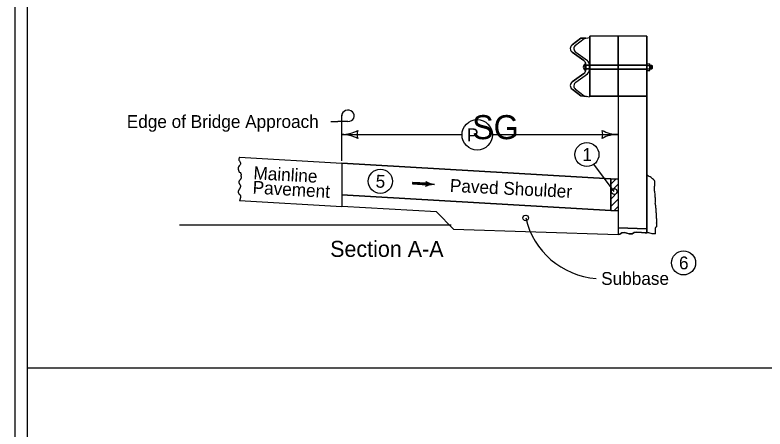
# Model space of a CAD drawing. Extents: x 9538 to 81668, y 7600 to 11751.
# Drawn here: x 13733 to 14667, y 8764 to 9280 of the extents above; entities that cross this region are included whole.
import ezdxf

# ---------------------------------------------------------------- set-up
doc = ezdxf.new("R2010")
doc.units = 0
for name, color, linetype in [('Default', 7, 'Continuous'), ('DsnShtMinorGrid13', 7, 'Continuous'), ('DsnShtMinorGrid14', 7, 'Continuous'), ('dsnStdCells', 7, 'Continuous'), ('dsnStdDimension', 7, 'Continuous'), ('dsnStdNameDate', 7, 'Continuous'), ('dsnStdNote', 7, 'Continuous'), ('dsnStdShading', 7, 'Continuous'), ('dsnStdTable', 7, 'Continuous')]:
    doc.layers.add(name, color=color, linetype=linetype)

msp = doc.modelspace()

# ---------------------------------------------------------------- linework, layer by layer
at = {"layer": 'Default'}
msp.add_lwpolyline([(13732.53, 9944.02), (16867.53, 9944.02), (16867.53, 7924.02), (13732.53, 7924.02)], close=True, dxfattribs=at)
at = {"layer": 'DsnShtMinorGrid13'}
for centre, radius in [((14444.79, 9106.23), 15), ((14187.58, 9072.86), 15), ((14478.92, 9060.11), 3.58), ((14565.23, 8971.18), 15)]:
    msp.add_circle(centre, radius, dxfattribs=at)
at = {"layer": 'DsnShtMinorGrid14'}
msp.add_circle((14368.6, 9027.15), 3.54, dxfattribs=at)
at = {"layer": 'dsnStdCells'}
for p, q in [((14426.56, 9233.67), (14441.07, 9223.26)), ((14441.07, 9207.18), (14426.56, 9196.77))]:
    msp.add_line(p, q, dxfattribs=at)
for points in [[(14430.81, 9242.57), (14430.8, 9242.56), (14441.57, 9250.97), (14443.46, 9251.3), (14437.13, 9251.19), (14426.37, 9242.79)], [(14483.85, 9217.88), (14483.85, 9253.55), (14448.31, 9253.55), (14448.31, 9217.88), (14448.31, 9217.88), (14483.85, 9217.88)], [(14519.4, 9217.88), (14519.4, 9221.88), (14519.4, 9253.55), (14483.85, 9253.55), (14483.85, 9217.88), (14519.4, 9217.88)], [(14445.51, 9223.04), (14445.54, 9223.02), (14430.98, 9233.48), (14431.01, 9233.45)], [(14443.46, 9218.63), (14443.46, 9217.55), (14447.91, 9217.55), (14447.91, 9218.41), (14447.91, 9218.41)], [(14447.91, 9211.6), (14447.91, 9211.6), (14447.91, 9212.88), (14443.47, 9212.88), (14443.47, 9211.82), (14443.47, 9212.88), (14443.46, 9212.88), (14443.46, 9211.82)], [(14448.31, 9217.55), (14448.31, 9212.88), (14448.31, 9212.88), (14483.85, 9212.88), (14483.85, 9217.55), (14448.31, 9217.55), (14448.31, 9217.55)], [(14448.31, 9212.55), (14448.31, 9178.9), (14483.85, 9178.9), (14483.85, 9212.55), (14448.31, 9212.55)], [(14519.4, 9212.88), (14519.4, 9217.55), (14483.85, 9217.55), (14483.85, 9212.88), (14519.4, 9212.88)], [(14519.4, 9178.9), (14519.4, 9208.55), (14519.4, 9212.55), (14483.85, 9212.55), (14483.85, 9178.9), (14519.4, 9178.9)], [(14431.01, 9196.55), (14430.98, 9196.53), (14445.54, 9206.99), (14445.51, 9206.96)], [(14426.37, 9187.65), (14437.13, 9179.25), (14444.23, 9178.56), (14441.57, 9179.03), (14430.8, 9187.44), (14430.81, 9187.43)], [(14519.4, 9013.57), (14519.4, 9178.9), (14483.85, 9178.9), (14483.85, 9075.94), (14483.85, 9069.25), (14483.85, 9069.25), (14483.85, 9069.25), (14483.85, 9060.02), (14483.85, 9060.02), (14483.85, 9060.02), (14483.85, 9050.88), (14483.85, 9050.88), (14483.85, 9050.88), (14483.85, 9043.95), (14483.85, 9014.73), (14519.4, 9013.57)], [(14519.4, 9013.57), (14483.85, 9014.73), (14483.85, 9006.67), (14485.66, 9006.92), (14488.42, 9008.51), (14491.71, 9009.04), (14497.32, 9007.45), (14501.03, 9007.24), (14503.68, 9009.04), (14506.76, 9009.68), (14513.01, 9008.94), (14517.25, 9008.51), (14519.4, 9008.51), (14519.4, 9013.57)]]:
    msp.add_lwpolyline(points, dxfattribs=at)
msp.add_lwpolyline([(14447.91, 9217.55), (14443.46, 9217.55), (14443.47, 9214.09), (14443.47, 9215.22), (14443.47, 9212.88), (14447.91, 9212.88)], close=True, dxfattribs=at)
for centre, start, end in [((14429.84, 9238.31), 127.75002, 234.69086), ((14434.29, 9238.09), 127.75002, 234.69086), ((14437.79, 9218.63), 0, 54.69099), ((14442.23, 9218.41), 0, 54.69099), ((14437.79, 9211.82), 305.30901, 0), ((14442.23, 9211.6), 305.30901, 0), ((14429.84, 9192.14), 125.30914, 232.24998), ((14434.29, 9191.92), 125.30914, 232.24998)]:
    msp.add_arc(centre, 5.68, start, end, dxfattribs=at)
at = {"layer": 'dsnStdDimension'}
for p, q in [((14139.46, 9131.19), (14289.29, 9131.19)), ((14327.15, 9131.34), (14483.85, 9131.34))]:
    msp.add_line(p, q, dxfattribs=at)
msp.add_circle((14308.22, 9130.78), 18.93, dxfattribs=at)
for centre, radius, start, end in [((14139.46, 9173.69), 42.5, 270, 298.07249), ((14175.1, 9131.19), 16.42, 162.26665, 197.73335), ((14448.22, 9131.34), 16.42, 342.26665, 17.73335), ((14483.85, 9173.84), 42.5, 241.92751, 270), ((14139.46, 9088.69), 42.5, 61.92751, 90), ((14483.85, 9088.84), 42.5, 90, 118.07249), ((14463.83, 9049.27), 97.76, 193.07698, 265.55799)]:
    msp.add_arc(centre, radius, start, end, dxfattribs=at)
at = {"layer": 'dsnStdNameDate'}
for p, q in [((14478.92, 9060.11), (14453.53, 9094.04)), ((15903.11, 8840.02), (13747.53, 8840.02))]:
    msp.add_line(p, q, dxfattribs=at)
at = {"layer": 'dsnStdNote'}
for p, q in [((14139.46, 9134.51), (14139.46, 9155.37)), ((14126.09, 9147.35), (14134.78, 9147.35)), ((14147.27, 9147.35), (14134.78, 9147.35)), ((14139.46, 9098.57), (14139.46, 9134.51)), ((14245.85, 9069.47), (14227.64, 9070.52)), ((14245.86, 9070.47), (14245.86, 9070.47)), ((14245.74, 9068.53), (14245.74, 9068.53))]:
    msp.add_line(p, q, dxfattribs=at)
for points in [[(14245.87, 9070.41), (14227.71, 9071.46), (14227.58, 9069.58), (14245.74, 9068.53), (14245.8, 9070.14), (14227.93, 9071.23), (14227.87, 9069.74), (14245.36, 9068.79), (14245.48, 9069.91), (14228.16, 9070.97), (14228.14, 9069.97), (14245.15, 9068.99), (14245.24, 9069.69), (14228.35, 9070.75), (14228.33, 9070.19), (14244.94, 9069.25)], [(14245.47, 9071.66), (14246.16, 9070.5), (14246.14, 9068.85), (14245.38, 9067.45), (14248.14, 9068.32), (14251.33, 9068.97), (14252.23, 9069.1), (14249.99, 9069.65), (14246.76, 9070.88), (14245.82, 9071.41), (14245.94, 9067.9), (14250.89, 9069.12), (14246.25, 9070.7), (14246.26, 9068.28), (14249.66, 9069.21), (14246.66, 9070.07), (14246.43, 9068.69), (14248.59, 9069.19), (14247, 9069.7), (14246.86, 9069.04), (14247.65, 9069.2)]]:
    msp.add_lwpolyline(points, dxfattribs=at)
for centre, major_axis, start_param, end_param in [((14147.27, 9154.49), (-7.81, 0), 1.570796, 6.283185), ((14242.08, 9069.68), (3.88, 0), 5.202895, 7.237436), ((14257.14, 9089.11), (-22.17, 0), 0.954258, 1.478381), ((14254.35, 9048.69), (22.17, 0), 1.537172, 2.061295)]:
    msp.add_ellipse(centre, major_axis=major_axis, ratio=0.913811, start_param=start_param, end_param=end_param, dxfattribs=at)
at = {"layer": 'dsnStdShading'}
msp.add_line((13747.53, 9929.02), (13747.53, 8319.02), dxfattribs=at)
at = {"layer": 'dsnStdTable'}
for p, q in [((14426.37, 9242.79), (14437.13, 9251.19)), ((14430.8, 9242.56), (14441.57, 9250.97)), ((14437.13, 9251.19), (14443.46, 9251.3)), ((14441.57, 9250.97), (14447.91, 9252.09)), ((14519.4, 9253.55), (14448.31, 9253.55)), ((14448.31, 9178.9), (14448.31, 9253.55)), ((14483.85, 9178.9), (14483.85, 9253.55)), ((14519.4, 9253.55), (14519.4, 9008.51)), ((14441.07, 9223.26), (14426.56, 9233.67)), ((14445.54, 9223.02), (14430.98, 9233.48)), ((14519.4, 9221.85), (14520.08, 9221.85)), ((14520.08, 9208.52), (14520.08, 9221.85)), ((14442.69, 9211.15), (14442.69, 9219.24)), ((14442.69, 9217.55), (14448.12, 9217.55)), ((14442.69, 9212.88), (14448.31, 9212.88)), ((14443.47, 9211.82), (14443.46, 9218.63)), ((14443.46, 9211.82), (14443.47, 9215.22)), ((14443.47, 9215.22), (14443.47, 9211.82)), ((14443.64, 9217.55), (14448.31, 9217.55)), ((14447.91, 9215), (14447.91, 9218.41)), ((14447.91, 9211.6), (14447.91, 9215)), ((14447.91, 9215), (14447.91, 9211.6)), ((14448.3, 9212.55), (14519.4, 9212.55)), ((14448.31, 9217.88), (14519.4, 9217.88)), ((14448.31, 9217.55), (14519.4, 9217.55)), ((14448.31, 9212.88), (14519.4, 9212.88)), ((14520.08, 9219.23), (14523.05, 9219.23)), ((14520.08, 9217.2), (14523.05, 9217.2)), ((14520.08, 9213.16), (14523.05, 9213.16)), ((14520.08, 9211.14), (14523.05, 9211.14)), ((14523.41, 9212.15), (14523.41, 9218.21)), ((14523.41, 9217.52), (14525.78, 9217.52)), ((14523.41, 9212.85), (14525.78, 9212.85)), ((14524.3, 9217.52), (14524.3, 9212.85)), ((14525.04, 9217.52), (14525.04, 9212.85)), ((14525.78, 9217.52), (14526.23, 9216.98)), ((14525.78, 9217.52), (14525.78, 9212.85)), ((14526.23, 9213.39), (14525.78, 9212.85)), ((14526.23, 9216.98), (14526.23, 9213.39)), ((14426.56, 9196.77), (14441.07, 9207.18)), ((14430.98, 9196.53), (14445.54, 9206.99)), ((14519.4, 9208.52), (14520.08, 9208.52)), ((14437.13, 9179.25), (14426.37, 9187.65)), ((14441.57, 9179.03), (14430.8, 9187.44)), ((14444.23, 9178.56), (14437.13, 9179.25)), ((14447.91, 9177.92), (14441.57, 9179.03)), ((14483.85, 9178.9), (14448.31, 9178.9)), ((14483.85, 9178.9), (14483.85, 9006.67)), ((14012, 9102.84), (14139.46, 9095.43)), ((14139.46, 9095.43), (14139.46, 9041.42)), ((14139.46, 9095.43), (14474.6, 9075.94)), ((14474.6, 9075.94), (14139.46, 9095.43)), ((14139.46, 9095.43), (14139.46, 9055.83)), ((14474.6, 9069.2), (14481.34, 9075.94)), ((14474.6, 9069.2), (14481.34, 9075.94)), ((14474.6, 9069.2), (14481.34, 9075.94)), ((14474.6, 9069.2), (14481.34, 9075.94)), ((14474.6, 9075.94), (14483.84, 9075.94)), ((14474.6, 9075.94), (14474.6, 9036.51)), ((14474.6, 9036.51), (14474.6, 9075.94)), ((14474.6, 9060.01), (14483.84, 9069.25)), ((14474.6, 9060.01), (14483.84, 9069.25)), ((14474.6, 9060.01), (14483.84, 9069.25)), ((14474.6, 9060.01), (14483.84, 9069.25)), ((14529.45, 9069.17), (14529.45, 9069.17)), ((14474.6, 9036.51), (14139.46, 9055.83)), ((14139.46, 9055.83), (14474.6, 9036.51)), ((14474.6, 9050.78), (14483.84, 9060.02)), ((14474.6, 9050.78), (14483.84, 9060.02)), ((14474.6, 9050.78), (14483.84, 9060.02)), ((14474.6, 9050.78), (14483.84, 9060.02)), ((14012.03, 9048.83), (14139.46, 9041.42)), ((14474.6, 9041.56), (14483.84, 9050.79)), ((14257.3, 9034.62), (14139.46, 9041.42)), ((14257.3, 9034.62), (14278.64, 9013.41)), ((14474.6, 9036.51), (14483.84, 9036.51)), ((14478.7, 9036.51), (14483.84, 9041.65)), ((13937.41, 9018.58), (14275.91, 9018.58)), ((14278.64, 9013.41), (14483.85, 9006.67))]:
    msp.add_line(p, q, dxfattribs=at)
for points in [[(14523.4, 9212.48), (14523.35, 9212.74), (14523.31, 9212.92), (14523.22, 9213.07), (14523.1, 9213.17), (14523.18, 9213.26), (14523.26, 9213.49), (14523.32, 9213.8), (14523.4, 9214.55), (14523.4, 9212.47), (14523.38, 9212.62), (14523.34, 9212.83), (14523.26, 9213.04), (14523.14, 9213.15), (14523.18, 9213.24), (14523.24, 9213.39), (14523.34, 9213.89), (14523.38, 9214.27), (14523.38, 9212.67), (14523.35, 9212.79), (14523.31, 9212.95), (14523.18, 9213.15), (14523.23, 9213.32), (14523.31, 9213.66), (14523.37, 9213.98), (14523.36, 9212.82), (14523.32, 9212.95), (14523.21, 9213.14), (14523.25, 9213.36), (14523.31, 9213.62), (14523.34, 9213.79), (14523.34, 9212.93), (14523.28, 9213.03), (14523.23, 9213.15), (14523.32, 9213.61), (14523.32, 9213.01), (14523.25, 9213.14), (14523.3, 9213.44), (14523.3, 9213.08), (14523.27, 9213.15), (14523.28, 9213.25), (14523.28, 9213.18)], [(14523.11, 9217.21), (14523.18, 9217.25), (14523.26, 9217.35), (14523.34, 9217.57), (14523.4, 9217.86), (14523.4, 9215.91), (14523.34, 9216.43), (14523.29, 9216.8), (14523.17, 9217.12), (14523.11, 9217.21), (14523.17, 9217.21), (14523.27, 9217.36), (14523.36, 9217.59), (14523.38, 9217.74), (14523.38, 9216.2), (14523.31, 9216.7), (14523.25, 9216.96), (14523.15, 9217.18), (14523.18, 9217.2), (14523.32, 9217.41), (14523.36, 9217.57), (14523.36, 9216.46), (14523.17, 9217.17), (14523.34, 9217.45), (14523.34, 9216.6), (14523.2, 9217.16), (14523.32, 9217.38), (14523.33, 9216.74), (14523.22, 9217.14), (14523.31, 9217.32), (14523.31, 9216.9), (14523.24, 9217.13), (14523.29, 9217.25), (14523.29, 9217.04), (14523.26, 9217.11), (14523.27, 9217.16)], [(14529.92, 9045.33), (14529.86, 9045.06), (14529.86, 9044.86), (14529.86, 9044.67), (14529.86, 9044.47), (14529.86, 9044.28), (14529.86, 9044.08), (14529.86, 9043.79), (14529.86, 9043.59), (14529.96, 9043.3), (14530.06, 9043.01), (14530.25, 9042.81), (14530.25, 9042.62), (14530.35, 9042.42), (14530.35, 9042.23), (14530.35, 9042.03), (14530.45, 9041.93), (14530.45, 9041.74), (14530.45, 9041.54), (14530.45, 9041.35), (14530.45, 9041.15), (14530.45, 9040.96), (14530.45, 9040.66), (14530.45, 9040.37), (14530.45, 9040.17), (14530.45, 9039.88), (14530.45, 9039.69), (14530.45, 9039.49), (14530.55, 9039.39), (14530.55, 9039.2), (14530.55, 9039), (14530.55, 9038.81), (14530.55, 9038.61), (14530.55, 9038.42), (14530.55, 9038.22), (14530.55, 9038.02), (14530.55, 9037.83), (14530.55, 9037.63), (14530.55, 9037.44), (14530.55, 9037.24), (14530.55, 9037.05), (14530.55, 9036.85), (14530.55, 9036.66), (14530.55, 9036.46), (14530.55, 9036.27), (14530.55, 9036.07), (14530.55, 9035.88), (14530.64, 9035.78), (14530.64, 9035.58), (14530.64, 9035.39), (14530.74, 9035.29), (14530.74, 9035.09), (14530.74, 9034.9), (14530.84, 9034.8), (14530.84, 9034.61), (14530.84, 9034.41), (14530.84, 9034.21), (14530.84, 9033.92), (14530.94, 9033.63), (14530.94, 9033.43), (14530.94, 9033.24), (14530.94, 9033.04), (14530.94, 9032.85), (14530.94, 9032.65), (14530.94, 9032.46), (14530.94, 9032.26), (14530.94, 9032.06), (14530.94, 9031.87), (14530.94, 9031.67), (14530.94, 9031.48), (14530.94, 9031.28), (14530.94, 9031.09), (14530.94, 9030.89), (14530.94, 9030.7), (14530.94, 9030.5), (14530.94, 9030.31), (14530.94, 9030.11), (14530.94, 9029.92), (14530.94, 9029.72), (14530.94, 9029.52), (14530.94, 9029.33), (14530.94, 9029.13), (14530.94, 9028.94), (14530.94, 9028.74), (14530.94, 9028.55), (14530.94, 9028.35), (14530.94, 9028.16), (14530.94, 9027.96), (14531.03, 9027.86), (14531.03, 9027.57), (14531.03, 9027.37), (14531.13, 9027.18), (14531.23, 9026.89), (14531.23, 9026.69), (14531.33, 9026.59), (14531.33, 9026.4), (14531.42, 9026.3), (14531.52, 9026.2), (14531.52, 9026.01), (14531.52, 9025.81), (14531.52, 9025.62), (14531.62, 9025.52), (14531.62, 9025.32), (14531.62, 9025.13), (14531.62, 9024.93), (14531.62, 9024.74), (14531.62, 9024.54), (14531.62, 9024.35), (14531.62, 9024.15), (14531.62, 9023.96), (14531.62, 9023.76), (14531.62, 9023.56), (14531.62, 9023.37), (14531.62, 9023.17), (14531.62, 9022.98), (14531.62, 9022.78), (14531.62, 9022.59), (14531.62, 9022.39), (14531.62, 9022.2), (14531.62, 9022), (14531.62, 9021.81), (14531.62, 9021.61), (14531.62, 9021.42), (14531.62, 9021.22), (14531.62, 9021.02), (14531.62, 9020.83), (14531.62, 9020.63), (14531.62, 9020.63), (14531.62, 9020.93), (14531.62, 9021.12), (14531.62, 9021.32), (14531.62, 9021.12), (14531.62, 9020.93), (14531.62, 9020.73), (14531.62, 9020.54), (14531.62, 9020.34), (14531.62, 9020.14), (14531.62, 9019.95), (14531.62, 9019.75), (14531.62, 9019.56), (14531.62, 9019.36), (14531.62, 9019.17), (14531.62, 9018.97), (14531.62, 9018.78), (14531.62, 9018.58), (14531.62, 9018.39), (14531.52, 9018.29), (14531.52, 9018.09), (14531.52, 9017.9), (14531.52, 9017.7), (14531.52, 9017.51), (14531.52, 9017.31), (14531.52, 9017.12), (14531.52, 9016.92), (14531.52, 9016.73), (14531.52, 9016.53), (14531.52, 9016.33), (14531.42, 9016.24), (14531.33, 9016.04), (14531.23, 9015.94), (14531.13, 9015.85), (14531.03, 9015.75), (14530.84, 9015.65), (14530.64, 9015.65), (14530.55, 9015.55), (14530.45, 9015.46), (14530.35, 9015.36), (14530.15, 9015.26), (14530.06, 9015.16), (14530.06, 9014.97), (14529.96, 9014.87), (14529.96, 9014.67), (14529.96, 9014.48), (14529.96, 9014.28), (14529.96, 9007.46)], [(14530.09, 9007.47), (14525.94, 9007.35), (14521.81, 9008.51), (14517.25, 9008.51), (14513.01, 9008.94), (14506.76, 9009.68), (14503.68, 9009.04), (14501.03, 9007.24), (14497.32, 9007.45), (14491.71, 9009.04), (14488.42, 9008.51), (14485.66, 9006.92), (14483.85, 9006.67)]]:
    msp.add_lwpolyline(points, dxfattribs=at)
msp.add_circle((14187.58, 9072.86), 15, dxfattribs=at)
for centre, radius, start, end in [((14429.84, 9238.31), 5.68, 127.75002, 234.69086), ((14434.29, 9238.09), 5.68, 127.75002, 234.69086), ((14437.79, 9218.63), 5.68, 360, 54.69099), ((14442.23, 9218.41), 5.68, 360, 54.69099), ((14444.77, 9215.2), 4.54, 117.20289, 242.8461), ((14437.79, 9211.82), 5.68, 305.30901, 0), ((14442.23, 9211.6), 5.68, 305.30901, 0), ((14429.84, 9192.14), 5.68, 125.30914, 232.24998), ((14434.29, 9191.92), 5.68, 125.30914, 232.24998)]:
    msp.add_arc(centre, radius, start, end, dxfattribs=at)
for centre in [(14523.05, 9218.21), (14523.05, 9212.15)]:
    msp.add_ellipse(centre, major_axis=(0, -1.01), ratio=0.362258, start_param=6.283156, end_param=9.424748, dxfattribs=at)
for points in [[(14012, 9102.84), (14011.5, 9099.24), (14012.54, 9097.73), (14013.4, 9095.44), (14012.8, 9093.38), (14010.89, 9091), (14010.37, 9089.1), (14010.89, 9086.8), (14011.76, 9084.43), (14012.8, 9083.72), (14014.18, 9081.18), (14014.17, 9080.34)], [(14012.21, 9063.23), (14012.42, 9063.48), (14012.62, 9063.74), (14012.97, 9064.3), (14013.25, 9064.89), (14013.37, 9065.19), (14013.47, 9065.51), (14013.6, 9066.13), (14013.65, 9066.75), (14013.6, 9067.34), (14013.54, 9067.61), (14013.51, 9067.75), (14013.46, 9067.88), (14013.25, 9068.26), (14012.97, 9068.62), (14012.67, 9068.99), (14012.42, 9069.38), (14012.28, 9069.67), (14012.14, 9069.95), (14011.88, 9070.52), (14011.68, 9071.09), (14011.61, 9071.38), (14011.55, 9071.68), (14011.54, 9071.81), (14011.54, 9071.94), (14011.69, 9072.71), (14011.9, 9073.23), (14012.16, 9073.74), (14012.6, 9074.38), (14013.12, 9074.92), (14013.64, 9075.47), (14013.87, 9075.78), (14014.07, 9076.12), (14014.27, 9076.59), (14014.43, 9077.06), (14014.53, 9077.54), (14014.57, 9077.78), (14014.58, 9077.9), (14014.59, 9078.02), (14014.54, 9078.53), (14014.39, 9079.04), (14014.34, 9079.17), (14014.28, 9079.29), (14014.23, 9079.42), (14014.21, 9079.55), (14014.17, 9080.34)], [(14529.92, 9045.33), (14530.24, 9048.24), (14530.02, 9053.1), (14529.58, 9058.85), (14528.91, 9063.27), (14529.13, 9066.59), (14529.58, 9070.79), (14528.91, 9073.89), (14526.7, 9075.88), (14524.71, 9077.65), (14522.5, 9078.75), (14520.29, 9080.08), (14519.41, 9080.74)], [(14012.21, 9063.23), (14011.99, 9062.99), (14011.75, 9062.76), (14011.51, 9062.52), (14011.33, 9062.25), (14011.19, 9061.97), (14011.05, 9061.68), (14010.79, 9061.11), (14010.68, 9060.83), (14010.58, 9060.54), (14010.51, 9060.25), (14010.48, 9060.1), (14010.46, 9059.95), (14010.47, 9059.44), (14010.6, 9058.92), (14010.81, 9058.4), (14011.07, 9057.89), (14011.51, 9057.26), (14012.03, 9056.71), (14012.55, 9056.16), (14012.78, 9055.86), (14012.98, 9055.52), (14013.38, 9054.57), (14013.49, 9054.1), (14013.5, 9053.62), (14013.46, 9053.33), (14013.41, 9053.04), (14013.36, 9052.75), (14013.29, 9052.47), (14012.98, 9051.32), (14012.8, 9050.71), (14012.6, 9050.11), (14012.38, 9049.52), (14012.25, 9049.23), (14012.11, 9048.94), (14012.03, 9048.83)]]:
    msp.add_spline(points, degree=3, dxfattribs=at)

# ---------------------------------------------------------------- texts
at = {"layer": 'DsnShtMinorGrid13'}
for s, p in [('1', (14439.17, 9098.23)), ('6', (14559.53, 8963.18))]:
    msp.add_text(s, height=16, dxfattribs=at).set_placement(p)
msp.add_text('5', height=16, rotation=356.69973, dxfattribs=at).set_placement((14181.36, 9065.2))
at = {"layer": 'dsnStdDimension'}
for s, height, p in [('SG', 30, (14301.94, 9125.34)), ('P', 16, (14295.51, 9122.78))]:
    msp.add_text(s, height=height, dxfattribs=at).set_placement(p)
at = {"layer": 'dsnStdNote'}
for s, height, p in [('Edge of Bridge Approach', 16, (13871.73, 9139.35)), ('Section A-A', 20, (14125.04, 8978.66)), ('Subbase', 16, (14462.61, 8943.8))]:
    msp.add_text(s, height=height, dxfattribs=at).set_placement(p)
for s, rotation, p in [('Mainline', 356.73462, (14029.22, 9075.55)), ('Pavement', 356.73462, (14028.19, 9057.58)), ('Paved Shoulder ', 357.0678, (14273.86, 9059.83))]:
    msp.add_text(s, height=16, rotation=rotation, dxfattribs=at).set_placement(p)

doc.saveas('drawing.dxf')
